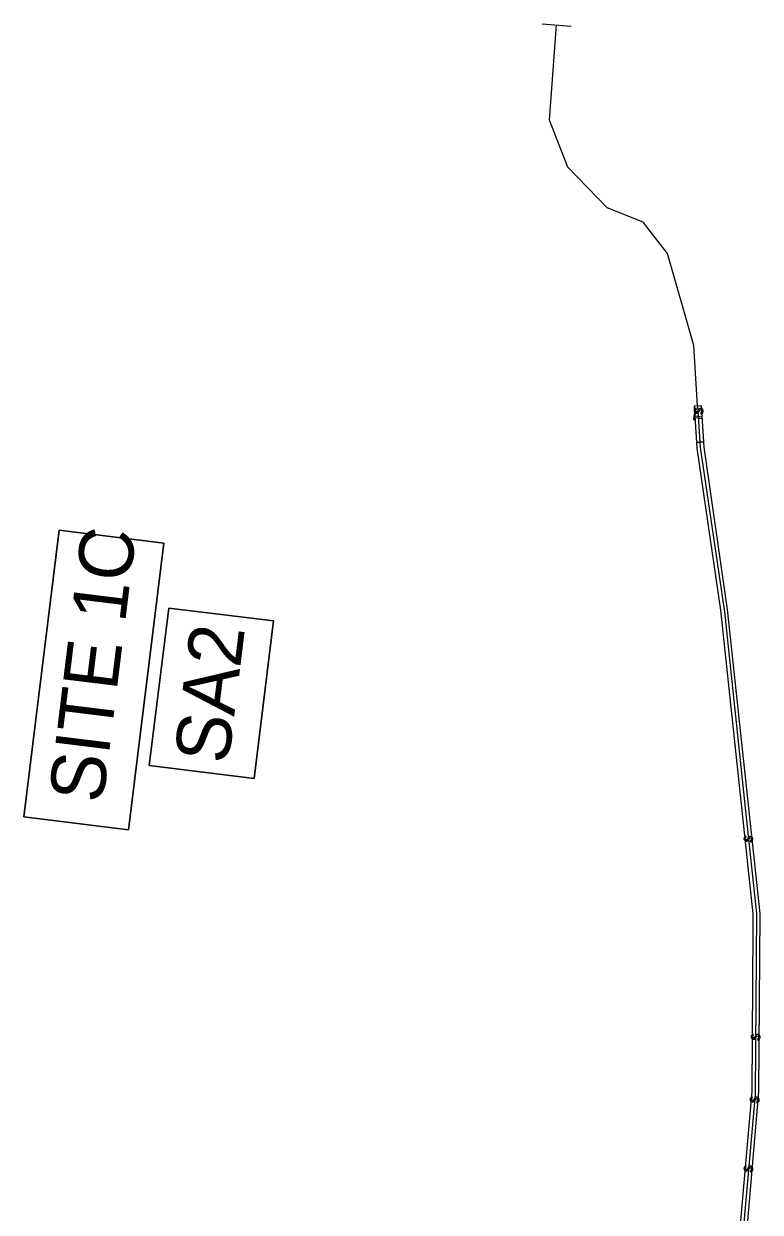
# Model space of a CAD drawing. Extents: x 474218 to 481634, y 484357 to 504997.
# Drawn here: x 480964.4 to 481167.4, y 489588 to 489915.6 of the extents above; entities that cross this region are included whole.
import ezdxf

# ---------------------------------------------------------------- set-up
doc = ezdxf.new("R2010")
doc.units = 0
for name, color, linetype in [('Exist Hydro Jurisdictional Stream or Body of Water', 7, 'Continuous'), ('Old_Level_29', 7, 'Continuous'), ('Prop Earthen Structure Impacts In Surface Waters Hatching CELL', 7, 'Continuous'), ('Prop Grid Mask', 7, 'Continuous'), ('Scratch_Level_4', 7, 'Continuous'), ('Temp Earthen Structure Impacts In Surface Waters Hatching CELL', 7, 'Continuous')]:
    doc.layers.add(name, color=color, linetype=linetype)

msp = doc.modelspace()

# ---------------------------------------------------------------- linework, layer by layer
at = {"layer": 'Exist Hydro Jurisdictional Stream or Body of Water'}
msp.add_lwpolyline([(480999, 489711.11), (481004.35, 489754.51), (481033.21, 489750.96), (481027.87, 489707.56)], close=True, dxfattribs=at)
at = {"layer": 'Old_Level_29'}
msp.add_lwpolyline([(480964.39, 489696.98), (480974.12, 489775.95), (481002.99, 489772.39), (480993.26, 489693.42)], close=True, dxfattribs=at)
at = {"layer": 'Prop Earthen Structure Impacts In Surface Waters Hatching CELL'}
for p, q in [((481151.83, 489800.37), (481149.84, 489800.15)), ((481149.84, 489800.15), (481149.94, 489798.62))]:
    msp.add_line(p, q, dxfattribs=at)
for points in [[(481149.94, 489798.62), (481156.44, 489753.9), (481165.41, 489670.22), (481165.38, 489666.03), (481165.05, 489621.29), (481160.81, 489572.04), (481151.04, 489547.37), (481156.66, 489522.19), (481148.66, 489499.12), (481146.05, 489474.55), (481143.68, 489460.85), (481134.96, 489437.37), (481130.87, 489405.08)], [(481132.18, 489404.97), (481136.91, 489436.87), (481145.62, 489460.32), (481148.03, 489474.28), (481150.62, 489498.68), (481158.73, 489522.07), (481153.13, 489547.2), (481162.77, 489571.58), (481167.05, 489621.2), (481167.41, 489670.32), (481158.43, 489754.15), (481151.93, 489798.83), (481151.83, 489800.37)]]:
    msp.add_lwpolyline(points, dxfattribs=at)
for points in [[(481162.96, 489690.78), (481162.96, 489690.75), (481163.04, 489691.33), (481163.03, 489691.32), (481162.95, 489691.04), (481162.95, 489691.04)], [(481163.58, 489690.26), (481163.66, 489690.26), (481163.72, 489690.7), (481163.62, 489690.66), (481163.49, 489690.67), (481163.49, 489690.67), (481163.46, 489690.68), (481163.38, 489690.73), (481163.35, 489690.76), (481163.32, 489690.81), (481163.3, 489690.84), (481163.3, 489690.86), (481163.29, 489690.92), (481163.28, 489690.99), (481163.36, 489691.64), (481163.32, 489691.63), (481163.19, 489691.54), (481163.16, 489691.51), (481163.04, 489691.33), (481162.96, 489690.75), (481163.04, 489690.57), (481163.07, 489690.52), (481163.17, 489690.42), (481163.21, 489690.38), (481163.23, 489690.37), (481163.24, 489690.35), (481163.24, 489690.35), (481163.26, 489690.34), (481163.3, 489690.33), (481163.33, 489690.32), (481163.41, 489690.29), (481163.44, 489690.27), (481163.45, 489690.27)], [(481163.44, 489691.29), (481163.54, 489691.35), (481163.47, 489691.52), (481163.45, 489691.58), (481163.42, 489691.66), (481163.4, 489691.65), (481163.4, 489691.65), (481163.38, 489691.65), (481163.36, 489691.64), (481163.28, 489690.99), (481163.32, 489691.16), (481163.34, 489691.18), (481163.35, 489691.18), (481163.37, 489691.21), (481163.41, 489691.27)], [(481163.81, 489690.31), (481163.86, 489690.33), (481163.94, 489690.95), (481163.88, 489690.84), (481163.76, 489690.72), (481163.72, 489690.7), (481163.66, 489690.26), (481163.7, 489690.27)], [(481165.04, 489690.92), (481165.04, 489690.77), (481165.12, 489691.42), (481165.1, 489691.44), (481165.1, 489691.44), (481165.09, 489691.44), (481165.05, 489691.48), (481165.03, 489691.49), (481165.02, 489691.49), (481164.95, 489691.51), (481164.92, 489691.52), (481164.9, 489691.53), (481164.81, 489691.56), (481164.76, 489691.56), (481164.63, 489691.56), (481164.57, 489691.57), (481164.52, 489691.54), (481164.42, 489691.5), (481164.42, 489691.5), (481164.35, 489691.47), (481164.3, 489691.42), (481164.17, 489691.29), (481164.13, 489691.25), (481164, 489691.05), (481163.94, 489690.95), (481163.86, 489690.33), (481163.92, 489690.37), (481164.04, 489690.46), (481164.07, 489690.5), (481164.21, 489690.68), (481164.26, 489690.77), (481164.35, 489690.9), (481164.46, 489691.06), (481164.51, 489691.1), (481164.58, 489691.15), (481164.71, 489691.18), (481164.77, 489691.17), (481164.85, 489691.15), (481164.88, 489691.13), (481164.9, 489691.11), (481164.97, 489691.07), (481164.98, 489691.04), (481164.99, 489691.01), (481165.03, 489690.94), (481165.04, 489690.93)], [(481165.3, 489690.4), (481165.39, 489690.71), (481165.38, 489691.05), (481165.38, 489691.05), (481165.26, 489691.29), (481165.25, 489691.32), (481165.12, 489691.42), (481165.04, 489690.77), (481165, 489690.6), (481165, 489690.59), (481164.99, 489690.58), (481164.93, 489690.5), (481164.91, 489690.47), (481164.89, 489690.46), (481164.82, 489690.41), (481164.78, 489690.39), (481164.76, 489690.38), (481164.67, 489690.36), (481164.73, 489690.16), (481164.75, 489690.11), (481164.77, 489690.04), (481164.84, 489690.06), (481164.86, 489690.06), (481164.88, 489690.06), (481164.93, 489690.07), (481164.93, 489690.07), (481164.93, 489690.08), (481164.96, 489690.09), (481165.11, 489690.17), (481165.12, 489690.18), (481165.3, 489690.39)], [(481164.96, 489636.18), (481164.96, 489636.15), (481165.03, 489636.73), (481165.02, 489636.72), (481164.95, 489636.44), (481164.95, 489636.43)], [(481165.57, 489635.66), (481165.66, 489635.66), (481165.71, 489636.1), (481165.62, 489636.06), (481165.49, 489636.07), (481165.48, 489636.07), (481165.45, 489636.08), (481165.37, 489636.12), (481165.34, 489636.16), (481165.31, 489636.21), (481165.3, 489636.24), (481165.29, 489636.25), (481165.29, 489636.31), (481165.28, 489636.39), (481165.35, 489637.04), (481165.31, 489637.02), (481165.18, 489636.93), (481165.15, 489636.91), (481165.03, 489636.73), (481164.96, 489636.15), (481165.04, 489635.96), (481165.06, 489635.92), (481165.16, 489635.82), (481165.2, 489635.78), (481165.22, 489635.76), (481165.23, 489635.75), (481165.24, 489635.75), (481165.25, 489635.74), (481165.29, 489635.73), (481165.32, 489635.72), (481165.4, 489635.68), (481165.43, 489635.67), (481165.44, 489635.67)], [(481165.44, 489636.69), (481165.53, 489636.74), (481165.47, 489636.92), (481165.44, 489636.98), (481165.41, 489637.06), (481165.4, 489637.05), (481165.39, 489637.05), (481165.37, 489637.04), (481165.35, 489637.04), (481165.28, 489636.39), (481165.31, 489636.55), (481165.33, 489636.58), (481165.34, 489636.58), (481165.36, 489636.61), (481165.41, 489636.67)], [(481165.8, 489635.71), (481165.86, 489635.72), (481165.93, 489636.35), (481165.87, 489636.24), (481165.75, 489636.12), (481165.71, 489636.1), (481165.66, 489635.66), (481165.7, 489635.67)], [(481167.03, 489636.32), (481167.04, 489636.17), (481167.12, 489636.82), (481167.09, 489636.84), (481167.09, 489636.84), (481167.09, 489636.84), (481167.04, 489636.88), (481167.03, 489636.88), (481167.01, 489636.89), (481166.95, 489636.91), (481166.92, 489636.92), (481166.89, 489636.93), (481166.81, 489636.96), (481166.75, 489636.96), (481166.62, 489636.96), (481166.56, 489636.96), (481166.51, 489636.94), (481166.42, 489636.9), (481166.42, 489636.9), (481166.34, 489636.87), (481166.29, 489636.82), (481166.16, 489636.69), (481166.13, 489636.64), (481166, 489636.45), (481165.93, 489636.35), (481165.86, 489635.72), (481165.91, 489635.77), (481166.03, 489635.86), (481166.06, 489635.9), (481166.2, 489636.08), (481166.26, 489636.17), (481166.34, 489636.3), (481166.45, 489636.46), (481166.51, 489636.5), (481166.57, 489636.55), (481166.71, 489636.58), (481166.76, 489636.56), (481166.85, 489636.54), (481166.87, 489636.53), (481166.9, 489636.51), (481166.96, 489636.47), (481166.97, 489636.44), (481166.99, 489636.41), (481167.02, 489636.33), (481167.03, 489636.32)], [(481167.29, 489635.79), (481167.38, 489636.11), (481167.37, 489636.44), (481167.37, 489636.44), (481167.25, 489636.68), (481167.24, 489636.71), (481167.12, 489636.82), (481167.04, 489636.17), (481166.99, 489635.99), (481166.99, 489635.99), (481166.98, 489635.98), (481166.92, 489635.9), (481166.9, 489635.86), (481166.89, 489635.85), (481166.81, 489635.81), (481166.78, 489635.79), (481166.75, 489635.78), (481166.66, 489635.76), (481166.73, 489635.56), (481166.74, 489635.51), (481166.77, 489635.44), (481166.84, 489635.45), (481166.85, 489635.46), (481166.87, 489635.46), (481166.92, 489635.47), (481166.93, 489635.47), (481166.93, 489635.47), (481166.95, 489635.49), (481167.1, 489635.57), (481167.12, 489635.58), (481167.29, 489635.79)], [(481164.67, 489618.9), (481164.67, 489618.87), (481164.74, 489619.44), (481164.73, 489619.44), (481164.66, 489619.15), (481164.66, 489619.15)], [(481165.28, 489618.38), (481165.37, 489618.38), (481165.42, 489618.82), (481165.33, 489618.78), (481165.2, 489618.78), (481165.19, 489618.78), (481165.16, 489618.8), (481165.08, 489618.84), (481165.05, 489618.88), (481165.02, 489618.93), (481165.01, 489618.95), (481165, 489618.97), (481165, 489619.03), (481164.99, 489619.11), (481165.06, 489619.75), (481165.02, 489619.74), (481164.89, 489619.65), (481164.86, 489619.63), (481164.74, 489619.44), (481164.67, 489618.87), (481164.75, 489618.68), (481164.77, 489618.63), (481164.87, 489618.53), (481164.91, 489618.5), (481164.93, 489618.48), (481164.94, 489618.47), (481164.95, 489618.47), (481164.96, 489618.46), (481165, 489618.44), (481165.03, 489618.43), (481165.11, 489618.4), (481165.14, 489618.39), (481165.15, 489618.39)], [(481165.15, 489619.4), (481165.24, 489619.46), (481165.18, 489619.64), (481165.15, 489619.69), (481165.12, 489619.77), (481165.11, 489619.77), (481165.1, 489619.77), (481165.08, 489619.76), (481165.06, 489619.75), (481164.99, 489619.11), (481165.02, 489619.27), (481165.04, 489619.29), (481165.05, 489619.3), (481165.07, 489619.33), (481165.12, 489619.39)], [(481165.51, 489618.42), (481165.57, 489618.44), (481165.64, 489619.06), (481165.58, 489618.96), (481165.46, 489618.84), (481165.42, 489618.82), (481165.37, 489618.38), (481165.41, 489618.39)], [(481166.74, 489619.03), (481166.75, 489618.88), (481166.83, 489619.53), (481166.8, 489619.55), (481166.8, 489619.55), (481166.8, 489619.56), (481166.75, 489619.6), (481166.74, 489619.6), (481166.72, 489619.61), (481166.66, 489619.63), (481166.63, 489619.64), (481166.6, 489619.65), (481166.52, 489619.68), (481166.46, 489619.68), (481166.33, 489619.68), (481166.27, 489619.68), (481166.22, 489619.66), (481166.13, 489619.62), (481166.13, 489619.62), (481166.05, 489619.59), (481166, 489619.54), (481165.87, 489619.41), (481165.84, 489619.36), (481165.71, 489619.17), (481165.64, 489619.06), (481165.57, 489618.44), (481165.62, 489618.48), (481165.74, 489618.58), (481165.77, 489618.62), (481165.91, 489618.8), (481165.97, 489618.88), (481166.05, 489619.02), (481166.16, 489619.18), (481166.22, 489619.22), (481166.28, 489619.27), (481166.42, 489619.29), (481166.47, 489619.28), (481166.56, 489619.26), (481166.58, 489619.25), (481166.61, 489619.23), (481166.67, 489619.18), (481166.68, 489619.16), (481166.7, 489619.13), (481166.73, 489619.05), (481166.74, 489619.04)], [(481167, 489618.51), (481167.09, 489618.83), (481167.08, 489619.16), (481167.08, 489619.16), (481166.96, 489619.4), (481166.95, 489619.43), (481166.83, 489619.53), (481166.75, 489618.88), (481166.7, 489618.71), (481166.7, 489618.71), (481166.69, 489618.7), (481166.63, 489618.61), (481166.61, 489618.58), (481166.6, 489618.57), (481166.52, 489618.52), (481166.49, 489618.5), (481166.46, 489618.5), (481166.37, 489618.47), (481166.44, 489618.28), (481166.45, 489618.22), (481166.48, 489618.16), (481166.55, 489618.17), (481166.56, 489618.17), (481166.58, 489618.18), (481166.63, 489618.19), (481166.64, 489618.19), (481166.64, 489618.19), (481166.66, 489618.21), (481166.81, 489618.28), (481166.83, 489618.29), (481167, 489618.51)], [(481162.97, 489599.88), (481162.97, 489599.86), (481163.04, 489600.43), (481163.04, 489600.42), (481162.96, 489600.14), (481162.96, 489600.14)], [(481163.58, 489599.37), (481163.67, 489599.37), (481163.73, 489599.81), (481163.63, 489599.77), (481163.5, 489599.77), (481163.49, 489599.77), (481163.46, 489599.79), (481163.38, 489599.83), (481163.36, 489599.87), (481163.33, 489599.92), (481163.31, 489599.94), (481163.31, 489599.96), (481163.3, 489600.02), (481163.29, 489600.1), (481163.37, 489600.74), (481163.33, 489600.73), (481163.2, 489600.64), (481163.17, 489600.62), (481163.04, 489600.43), (481162.97, 489599.86), (481163.05, 489599.67), (481163.07, 489599.62), (481163.18, 489599.52), (481163.22, 489599.49), (481163.23, 489599.47), (481163.25, 489599.46), (481163.25, 489599.46), (481163.27, 489599.45), (481163.31, 489599.43), (481163.33, 489599.42), (481163.42, 489599.39), (481163.45, 489599.38), (481163.45, 489599.38)], [(481163.45, 489600.39), (481163.55, 489600.45), (481163.48, 489600.62), (481163.46, 489600.68), (481163.43, 489600.76), (481163.41, 489600.76), (481163.41, 489600.76), (481163.39, 489600.75), (481163.37, 489600.74), (481163.29, 489600.1), (481163.33, 489600.26), (481163.35, 489600.28), (481163.35, 489600.29), (481163.38, 489600.32), (481163.42, 489600.37)], [(481163.82, 489599.41), (481163.87, 489599.43), (481163.95, 489600.05), (481163.88, 489599.95), (481163.77, 489599.82), (481163.73, 489599.81), (481163.67, 489599.36), (481163.71, 489599.38)], [(481165.05, 489600.02), (481165.05, 489599.87), (481165.13, 489600.52), (481165.11, 489600.54), (481165.11, 489600.54), (481165.1, 489600.55), (481165.06, 489600.58), (481165.04, 489600.59), (481165.03, 489600.6), (481164.96, 489600.62), (481164.93, 489600.63), (481164.91, 489600.64), (481164.82, 489600.67), (481164.77, 489600.67), (481164.63, 489600.67), (481164.58, 489600.67), (481164.53, 489600.65), (481164.43, 489600.61), (481164.43, 489600.61), (481164.36, 489600.58), (481164.31, 489600.53), (481164.17, 489600.4), (481164.14, 489600.35), (481164.01, 489600.16), (481163.95, 489600.05), (481163.87, 489599.43), (481163.93, 489599.47), (481164.05, 489599.57), (481164.08, 489599.61), (481164.21, 489599.78), (481164.27, 489599.87), (481164.36, 489600.01), (481164.47, 489600.17), (481164.52, 489600.21), (481164.58, 489600.26), (481164.72, 489600.28), (481164.77, 489600.27), (481164.86, 489600.25), (481164.88, 489600.24), (481164.91, 489600.22), (481164.98, 489600.17), (481164.99, 489600.15), (481165, 489600.12), (481165.04, 489600.04), (481165.04, 489600.03)], [(481165.31, 489599.5), (481165.4, 489599.81), (481165.39, 489600.15), (481165.39, 489600.15), (481165.27, 489600.39), (481165.25, 489600.42), (481165.13, 489600.52), (481165.05, 489599.87), (481165.01, 489599.7), (481165, 489599.7), (481165, 489599.69), (481164.94, 489599.6), (481164.92, 489599.57), (481164.9, 489599.56), (481164.83, 489599.51), (481164.79, 489599.49), (481164.77, 489599.49), (481164.68, 489599.46), (481164.74, 489599.27), (481164.76, 489599.21), (481164.78, 489599.15), (481164.85, 489599.16), (481164.87, 489599.16), (481164.89, 489599.17), (481164.93, 489599.18), (481164.94, 489599.18), (481164.94, 489599.18), (481164.97, 489599.19), (481165.11, 489599.27), (481165.13, 489599.28), (481165.31, 489599.5)]]:
    msp.add_lwpolyline(points, close=True, dxfattribs=at)
at = {"layer": 'Prop Grid Mask'}
for points in [[(480993.26, 489693.42), (481002.99, 489772.39), (480974.12, 489775.95), (480964.39, 489696.98)], [(481027.87, 489707.56), (481033.21, 489750.96), (481004.35, 489754.51), (480999, 489711.11)]]:
    msp.add_lwpolyline(points, close=True, dxfattribs=at)
at = {"layer": 'Scratch_Level_4'}
for p, q in [((481107.27, 489915.57), (481115.26, 489914.89)), ((481110.5, 489905.26), (481111.27, 489915.23))]:
    msp.add_line(p, q, dxfattribs=at)
for points in [[(481150.13, 489810.23), (481149.15, 489826.87), (481141.82, 489852.21), (481135.17, 489860.88), (481125.2, 489864.86), (481114.39, 489876.07), (481109.28, 489889.03), (481110.5, 489905.26)], [(481150.13, 489810.23), (481150.13, 489810.23), (481150.73, 489800.25)], [(481150.73, 489800.25), (481150.82, 489798.75), (481157.56, 489753.5), (481163.02, 489702.06), (481166.39, 489670.29), (481166.22, 489645.86), (481166.05, 489620.43), (481162.62, 489581.94), (481161.73, 489571.83), (481152.09, 489547.14), (481157.76, 489522.15), (481149.57, 489498.91), (481147.08, 489475.19), (481144.63, 489460.5), (481135.95, 489437.17), (481133.76, 489421.53), (481131.56, 489405.02)]]:
    msp.add_lwpolyline(points, dxfattribs=at)
at = {"layer": 'Temp Earthen Structure Impacts In Surface Waters Hatching CELL'}
for p, q in [((481151.21, 489810.3), (481149.22, 489810.18)), ((481149.22, 489810.18), (481149.84, 489800.15)), ((481151.83, 489800.37), (481151.21, 489810.3)), ((481149.84, 489800.15), (481151.83, 489800.37))]:
    msp.add_line(p, q, dxfattribs=at)
for points in [[(481149, 489806.47), (481149.32, 489806.43), (481149.52, 489808.04), (481149.19, 489808.08)], [(481149.26, 489808.75), (481149.26, 489808.72), (481149.33, 489809.3), (481149.33, 489809.29), (481149.25, 489809.01), (481149.25, 489809.01)], [(481149.87, 489808.24), (481149.96, 489808.23), (481150.01, 489808.67), (481149.92, 489808.63), (481149.79, 489808.64), (481149.78, 489808.64), (481149.75, 489808.65), (481149.67, 489808.7), (481149.65, 489808.73), (481149.62, 489808.78), (481149.6, 489808.81), (481149.6, 489808.83), (481149.59, 489808.89), (481149.58, 489808.97), (481149.66, 489809.61), (481149.62, 489809.6), (481149.49, 489809.51), (481149.46, 489809.48), (481149.33, 489809.3), (481149.26, 489808.72), (481149.34, 489808.54), (481149.36, 489808.49), (481149.47, 489808.39), (481149.5, 489808.35), (481149.52, 489808.34), (481149.54, 489808.32), (481149.54, 489808.32), (481149.56, 489808.32), (481149.6, 489808.3), (481149.62, 489808.29), (481149.71, 489808.26), (481149.74, 489808.24), (481149.74, 489808.24)], [(481149.74, 489809.26), (481149.83, 489809.32), (481149.77, 489809.49), (481149.75, 489809.55), (481149.72, 489809.63), (481149.7, 489809.62), (481149.69, 489809.62), (481149.68, 489809.62), (481149.66, 489809.61), (481149.58, 489808.96), (481149.62, 489809.13), (481149.64, 489809.15), (481149.64, 489809.16), (481149.66, 489809.18), (481149.71, 489809.24)], [(481150.11, 489808.28), (481150.16, 489808.3), (481150.24, 489808.92), (481150.17, 489808.81), (481150.06, 489808.69), (481150.01, 489808.67), (481149.96, 489808.23), (481150, 489808.24)], [(481151.33, 489808.89), (481151.34, 489808.74), (481151.42, 489809.39), (481151.4, 489809.41), (481151.4, 489809.41), (481151.39, 489809.41), (481151.35, 489809.45), (481151.33, 489809.46), (481151.32, 489809.46), (481151.25, 489809.48), (481151.22, 489809.49), (481151.2, 489809.5), (481151.11, 489809.53), (481151.06, 489809.53), (481150.92, 489809.53), (481150.87, 489809.54), (481150.82, 489809.51), (481150.72, 489809.48), (481150.72, 489809.47), (481150.65, 489809.44), (481150.59, 489809.39), (481150.46, 489809.26), (481150.43, 489809.22), (481150.3, 489809.02), (481150.24, 489808.92), (481150.16, 489808.3), (481150.22, 489808.34), (481150.34, 489808.43), (481150.37, 489808.47), (481150.5, 489808.65), (481150.56, 489808.74), (481150.65, 489808.87), (481150.76, 489809.03), (481150.81, 489809.07), (481150.87, 489809.12), (481151.01, 489809.15), (481151.06, 489809.14), (481151.15, 489809.12), (481151.17, 489809.1), (481151.2, 489809.08), (481151.26, 489809.04), (481151.28, 489809.01), (481151.29, 489808.98), (481151.33, 489808.91), (481151.33, 489808.9)], [(481151.6, 489808.37), (481151.68, 489808.68), (481151.67, 489809.02), (481151.67, 489809.02), (481151.56, 489809.26), (481151.54, 489809.29), (481151.42, 489809.39), (481151.34, 489808.74), (481151.29, 489808.57), (481151.29, 489808.56), (481151.29, 489808.55), (481151.23, 489808.47), (481151.21, 489808.44), (481151.19, 489808.43), (481151.11, 489808.38), (481151.08, 489808.36), (481151.06, 489808.35), (481150.97, 489808.33), (481151.03, 489808.13), (481151.05, 489808.08), (481151.07, 489808.01), (481151.14, 489808.03), (481151.16, 489808.03), (481151.17, 489808.03), (481151.22, 489808.04), (481151.23, 489808.05), (481151.23, 489808.05), (481151.26, 489808.06), (481151.4, 489808.14), (481151.42, 489808.15), (481151.59, 489808.36)], [(481149.4, 489807.05), (481151.39, 489806.81), (481151.44, 489807.18), (481149.44, 489807.43)]]:
    msp.add_lwpolyline(points, close=True, dxfattribs=at)

# ---------------------------------------------------------------- texts
at = {"layer": 'Exist Hydro Jurisdictional Stream or Body of Water'}
msp.add_text('SA2', height=15, rotation=82.9799, dxfattribs=at).set_placement((481020.75, 489711.25))
at = {"layer": 'Old_Level_29'}
msp.add_text('SITE 1C', height=15, rotation=82.9799, dxfattribs=at).set_placement((480986.17, 489700.45))

doc.saveas('drawing.dxf')
